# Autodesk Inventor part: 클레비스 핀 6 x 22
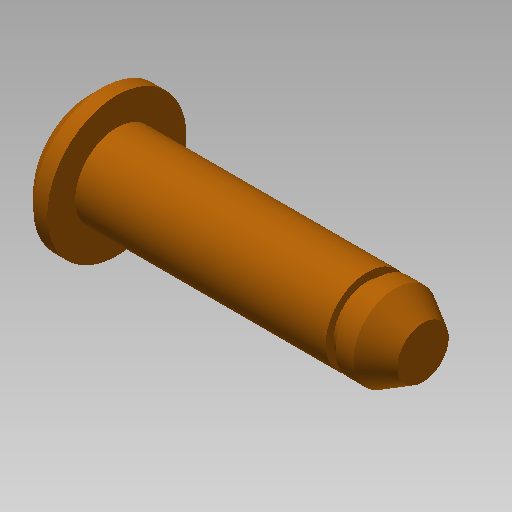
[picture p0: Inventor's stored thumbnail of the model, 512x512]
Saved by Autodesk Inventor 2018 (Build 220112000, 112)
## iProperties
IsCustomPart: 1
Created: 2017-08
Part Number: 클레비스 핀 6 x 22
Material: 강철
Description: 머리가 있는 클레비스 핀
Document SubType Name: Modeling
Standard: ISO 2341
Designer: mduedu
Standard Revision: Second edition 1986-11-01
Standards Organization: ISO
Language: ko-KR
Size Designation: B - 6 x 24
Categories: <MemberInstance><Categories><Category DisplayName="조임쇠" InternalName="e4da775c-781d-43d5-af7c-5136215cf5a6" Mnemonic="FSTN"><Category DisplayName="핀" InternalNa
Density: 7.85 g/cm^3
Appearance: 주황색
Author: mduedu
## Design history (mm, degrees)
sketch "스케치1"
  geometry: L1 (-2, 0)-(-2, 5); L2 (-2, 5)-(0, 5); L3 (0, 5)-(0, 3); L4 (0, 3)-(22, 3); L5 (22, 3)-(22, 0); L6 (-2, 0)-(22, 0); L7 (-7, 0)-(28, 0) reference; L8 (0, -1.96)-(0, 6.16) reference; C1 r 0.8 at (18.8, 0)
  constraints: 12 end point, 3 parallel, 2 collinear, 2 perpendicular, 1 centre point, 1 point on line, 1 vertical
  dimensions: "d0" = 6 diameter of L4 L6 (= NND); "d1" = 10 diameter of L2 L6 (= KOD); "d2" = 2 distance of L1.end L2.end (= KOH); "d3" = 22 distance of L3.end L4.end (= NLG); "d5" = 3.2 distance from line of L5 C1.centre (= DIST); "d6" = 1.6 diameter of C1 (= BOR)
revolve "본체" stored, may be unused: angle "d4" = 90 deg
workplane "Work Plane1"
node "작업 평면4"
sketch "스케치2"
  geometry: C1 r 3 at (0, 0) reference; C2 r 2.425 at (0, 0); 1 further point
  constraints: 1 centre point, 1 coincident
  dimensions: "d33" = 4.85 diameter of C2
extrude "돌출2" cut sketch "스케치2" distance "d34" = 0.7; taper "d35" = 0 deg
body "Solid1"
chamfer "모따기1" distance "d9" = 1 (= PHH2); stored, may be unused: angle "d10" = 45 deg (= FAWI2), second distance "d16" = 1 (= PHH2)
chamfer "모따기2" distance "d11" = 2 (= PHH1); stored, may be unused: angle "d12" = 30 deg (= FAWI1), second distance "d17" = 2 (= PHH1)
other parameters: "PHH1" = 2 [user parameter; used in 2 equation terms], "PHH2" = 1 [user parameter; used in 2 equation terms], "KOD" = 10 [user parameter; used in 1 equation term], "KOH" = 2 [user parameter; used in 1 equation term], "NND" = 6 [user parameter; used in 1 equation term], "FAWI1" = 30 deg [user parameter; used in 1 equation term], "FAWI2" = 45 deg [user parameter; used in 1 equation term], "DIST" = 3.2 [user parameter; used in 1 equation term], "BOR" = 1.6 [user parameter; used in 1 equation term], "NLG" = 22 [user parameter; used in 1 equation term], "d13" = 0, "d14" = 0, "d30" = 0, "d32" = 18
